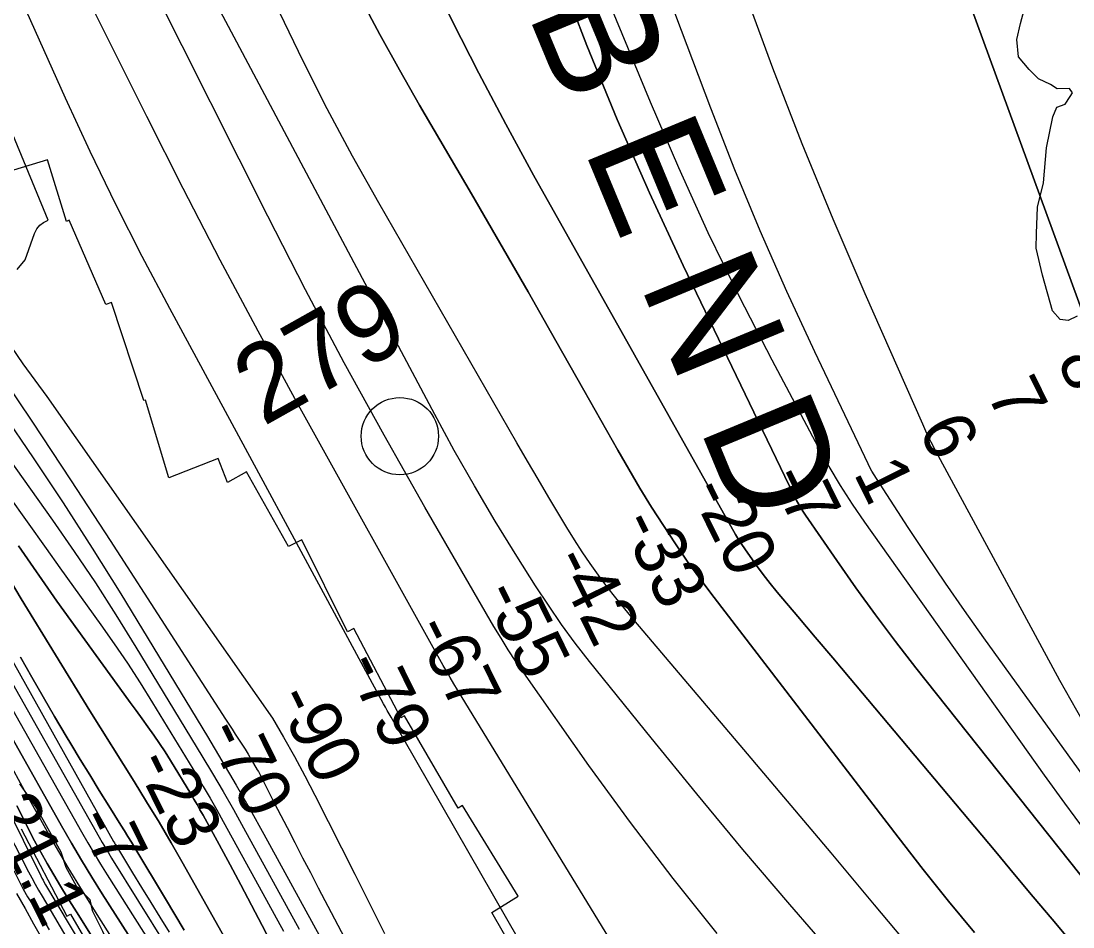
# Model space of a CAD drawing. Extents: x 3187622 to 3225504, y 800805 to 826213.
# Drawn here: x 3198035 to 3199396, y 818665 to 819837 of the extents above; entities that cross this region are included whole.
import ezdxf

# ---------------------------------------------------------------- set-up
doc = ezdxf.new("R2010")
doc.units = 0
for name, color, linetype in [('V-RIVR-EDGE', 7, 'Continuous'), ('V-RIVR-IDEN', 7, 'Continuous'), ('V-RIVR-MILE', 7, 'Continuous'), ('V-RIVR-RANG', 7, 'Continuous'), ('V-RRAP-RVMT', 7, 'Continuous'), ('V-SITE-VEGE', 7, 'Continuous'), ('V-TOPO-DPTH', 7, 'Continuous'), ('V-TOPO-MAJR', 7, 'Continuous'), ('V-TOPO-MINR', 7, 'Continuous'), ('V-TOPO-WATR', 7, 'Continuous')]:
    doc.layers.add(name, color=color, linetype=linetype)

msp = doc.modelspace()

# ---------------------------------------------------------------- linework, layer by layer
at = {"layer": 'V-RIVR-EDGE'}
for points in [[(3199401.5, 819455.2), (3199389.8, 819449.6), (3199379.3, 819450.9), (3199369.4, 819462.3), (3199356.4, 819508.4), (3199348.3, 819543.2), (3199348.7, 819562.3), (3199350.1, 819596.2), (3199358, 819627.9), (3199361.6, 819673.1), (3199370, 819713.1), (3199375.2, 819725.7), (3199385.7, 819729.5), (3199392.2, 819739.5), (3199395.3, 819744.3), (3199391.4, 819750), (3199375.7, 819749.6), (3199367, 819755.2), (3199351.4, 819762.2), (3199339.3, 819774.4), (3199325.4, 819791), (3199323.3, 819813.2), (3199328.1, 819834), (3199332.9, 819851.8)], [(3198032.9, 818850.3), (3198055, 818818.9), (3198086.6, 818762.3), (3198093.1, 818742.3), (3198106.5, 818718.4), (3198123.9, 818700.5), (3198126.9, 818686.2), (3198140.3, 818659.6), (3198150.7, 818637.9), (3198153.7, 818624.8), (3198170.2, 818619.1), (3198180.6, 818600.4), (3198185.3, 818583.4), (3198198.3, 818559.9)]]:
    msp.add_lwpolyline(points, dxfattribs=at)
at = {"layer": 'V-RIVR-MILE'}
msp.add_circle((3198525.1, 819300), 50, dxfattribs=at)
at = {"layer": 'V-RRAP-RVMT'}
for p, q in [((3198069.1, 819657.7), (3198025.3, 819644.3)), ((3198093.6, 819577.8), (3198069.1, 819657.7)), ((3198097.4, 819579.5), (3198093.6, 819577.8)), ((3198144.8, 819470.4), (3198097.4, 819579.5)), ((3198152, 819472.8), (3198144.8, 819470.4)), ((3198193.7, 819346.2), (3198152, 819472.8)), ((3198196, 819346.8), (3198193.7, 819346.2)), ((3198226.1, 819246), (3198196, 819346.8)), ((3198289.9, 819271), (3198226.1, 819246)), ((3198302, 819240.3), (3198289.9, 819271)), ((3198326.8, 819254.1), (3198302, 819240.3)), ((3198381.1, 819157.2), (3198326.8, 819254.1)), ((3198398.4, 819165.8), (3198381.1, 819157.2)), ((3198457.3, 819047), (3198398.4, 819165.8)), ((3198465.6, 819051.2), (3198457.3, 819047)), ((3198526.5, 818935.5), (3198465.6, 819051.2)), ((3198531, 818938.2), (3198526.5, 818935.5)), ((3198600.4, 818818.8), (3198531, 818938.2)), ((3198606.1, 818822.3), (3198600.4, 818818.8)), ((3198678.1, 818704.9), (3198606.1, 818822.3)), ((3198035, 818791.8), (3198094.1, 818679)), ((3198644.3, 818683.7), (3198678.1, 818704.9)), ((3198094.1, 818679), (3198099, 818681.6)), ((3198099, 818681.6), (3198172, 818556)), ((3198712.3, 818564.4), (3198644.3, 818683.7))]:
    msp.add_line(p, q, dxfattribs=at)
at = {"layer": 'V-SITE-VEGE'}
for p, q in [((3198025.5, 818738.3), (3198037.9, 818713.8)), ((3198037.9, 818713.8), (3198043.2, 818704.1)), ((3198043.2, 818704.1), (3198051.4, 818691.7)), ((3198051.4, 818691.7), (3198054.7, 818686.8)), ((3198054.7, 818686.8), (3198060.8, 818679.2)), ((3198060.8, 818679.2), (3198064.1, 818674)), ((3198064.1, 818674), (3198071.5, 818661.5))]:
    msp.add_line(p, q, dxfattribs=at)
at = {"layer": 'V-TOPO-DPTH'}
for points in [[(3198519, 820692.6), (3198538.7, 820598.2), (3198560.1, 820504.1), (3198646.5, 820144.6), (3198652.7, 820120.9), (3198659.4, 820097.4), (3198666.9, 820074.1), (3198675, 820050.9), (3198729.9, 819902.4), (3198767.2, 819805.7), (3198806.3, 819709.8), (3198848.1, 819615), (3198891.7, 819521), (3199035, 819223.7), (3199038.4, 819217), (3199042, 819210.5), (3199045.8, 819204.1), (3199049.9, 819197.8), (3199090.3, 819139), (3199115, 819103.7), (3199140.3, 819068.8), (3199166.3, 819034.4), (3199192.8, 819000.3), (3199485.2, 818632.6)], [(3199485.2, 818632.6), (3199192.8, 819000.3), (3199166.3, 819034.4), (3199140.3, 819068.8), (3199115, 819103.7), (3199090.3, 819139), (3199049.9, 819197.8), (3199045.8, 819204.1), (3199042, 819210.5), (3199038.4, 819217), (3199035, 819223.7), (3198891.7, 819521), (3198848.1, 819615), (3198806.3, 819709.8), (3198767.2, 819805.7), (3198729.9, 819902.4), (3198675, 820050.9), (3198666.9, 820074.1), (3198659.4, 820097.4), (3198652.7, 820120.9), (3198646.5, 820144.6), (3198560.1, 820504.1), (3198538.7, 820598.2), (3198519, 820692.6)], [(3199048.9, 820667.9), (3199069.1, 820567.3), (3199090.1, 820466.9), (3199124.2, 820309.6), (3199129.1, 820288.1), (3199134.3, 820266.6), (3199140, 820245.3), (3199146, 820224), (3199173.7, 820129.8), (3199194.4, 820061.6), (3199216, 819993.8), (3199238.9, 819926.4), (3199262.7, 819859.3), (3199420, 819428.5)], [(3199048.9, 820667.9), (3199069.1, 820567.3), (3199090.1, 820466.9), (3199124.2, 820309.6), (3199129.1, 820288.1), (3199134.3, 820266.6), (3199140, 820245.3), (3199146, 820224), (3199173.7, 820129.8), (3199194.4, 820061.6), (3199216, 819993.8), (3199238.9, 819926.4), (3199262.7, 819859.3), (3199420, 819428.5)], [(3199525.8, 818699.1), (3199280.7, 819039.1), (3199255.6, 819074.4), (3199230.9, 819109.9), (3199206.7, 819145.8), (3199182.8, 819181.9), (3199141.6, 819245.3), (3199138.7, 819249.9), (3199135.9, 819254.6), (3199133.3, 819259.4), (3199130.9, 819264.3), (3199061.8, 819409.3), (3199025.9, 819487.1), (3198991.3, 819565.6), (3198958.7, 819644.8), (3198927.4, 819724.6), (3198781.7, 820111)], [(3199525.8, 818699.1), (3199280.7, 819039.1), (3199255.6, 819074.4), (3199230.9, 819109.9), (3199206.7, 819145.8), (3199182.8, 819181.9), (3199141.6, 819245.3), (3199138.7, 819249.9), (3199135.9, 819254.6), (3199133.3, 819259.4), (3199130.9, 819264.3), (3199061.8, 819409.3), (3199025.9, 819487.1), (3198991.3, 819565.6), (3198958.7, 819644.8), (3198927.4, 819724.6), (3198781.7, 820111)], [(3198560.7, 819904), (3198593.4, 819836.6), (3198627.1, 819769.7), (3198662.1, 819703.6), (3198698.1, 819637.9), (3198959.4, 819172.7), (3198960.7, 819170.6), (3198963.2, 819166.4), (3198964.6, 819164.4), (3198978.2, 819144.5), (3198986.5, 819132.6), (3198995.1, 819121), (3199004.1, 819109.6), (3199013.2, 819098.4), (3199039.9, 819066.9), (3199062.6, 819040.1), (3199085.2, 819013.2), (3199107.8, 818986.3), (3199130.4, 818959.4), (3199296, 818762.1), (3199320.3, 818733.1), (3199344.6, 818704.2), (3199368.9, 818675.2), (3199393.2, 818646.3)], [(3199393.2, 818646.3), (3199368.9, 818675.2), (3199344.6, 818704.2), (3199320.3, 818733.1), (3199296, 818762.1), (3199130.4, 818959.4), (3199107.8, 818986.3), (3199085.2, 819013.2), (3199062.6, 819040.1), (3199039.9, 819066.9), (3199013.2, 819098.4), (3199004.1, 819109.6), (3198995.1, 819121), (3198986.5, 819132.6), (3198978.2, 819144.5), (3198964.6, 819164.4), (3198963.2, 819166.4), (3198960.7, 819170.6), (3198959.4, 819172.7), (3198698.1, 819637.9), (3198662.1, 819703.6), (3198627.1, 819769.7), (3198593.4, 819836.6), (3198560.7, 819904)], [(3198474.5, 819866.1), (3198499.1, 819819.8), (3198524.5, 819774), (3198550.4, 819728.5), (3198617.7, 819613.4), (3198654.4, 819550.1), (3198690.9, 819486.8), (3198727.1, 819423.3), (3198763.2, 819359.6), (3198807, 819281.9), (3198821.2, 819257.2), (3198835.7, 819232.7), (3198850.7, 819208.4), (3198866, 819184.3), (3198881.7, 819160.6), (3198897.9, 819137.1), (3198914.6, 819114), (3198931.7, 819091.2), (3199169.7, 818781.2), (3199202.2, 818739.6), (3199235.1, 818698.5), (3199268.7, 818657.9)], [(3199268.7, 818657.9), (3199235.1, 818698.5), (3199202.2, 818739.6), (3199169.7, 818781.2), (3198931.7, 819091.2), (3198914.6, 819114), (3198897.9, 819137.1), (3198881.7, 819160.6), (3198866, 819184.3), (3198850.7, 819208.4), (3198835.7, 819232.7), (3198821.2, 819257.2), (3198807, 819281.9), (3198763.2, 819359.6), (3198727.1, 819423.3), (3198690.9, 819486.8), (3198654.4, 819550.1), (3198617.7, 819613.4), (3198550.4, 819728.5), (3198524.5, 819774), (3198499.1, 819819.8), (3198474.5, 819866.1)], [(3198379, 818508.1), (3198244.6, 818746.8), (3198229.2, 818773.7), (3198213.6, 818800.5), (3198197.5, 818827), (3198181.3, 818853.4), (3198124.1, 818944.8), (3198079.4, 819017), (3198035.2, 819089.5), (3197991.7, 819162.4)], [(3197991.7, 819162.4), (3198035.2, 819089.5), (3198079.4, 819017), (3198124.1, 818944.8), (3198181.3, 818853.4), (3198197.5, 818827), (3198213.6, 818800.5), (3198229.2, 818773.7), (3198244.6, 818746.8), (3198379, 818508.1)], [(3198393.1, 818577.3), (3198347, 818666.8), (3198333.3, 818693.2), (3198319.5, 818719.4), (3198305.5, 818745.6), (3198291.3, 818771.7), (3198270.4, 818809.9), (3198266.5, 818816.8), (3198262.7, 818823.6), (3198258.7, 818830.4), (3198254.6, 818837.2), (3198228.4, 818880.4), (3198221.4, 818891.5), (3198214.3, 818902.5), (3198206.9, 818913.3), (3198199.2, 818923.9), (3198191.5, 818934.5), (3198183.8, 818945.1), (3198176.1, 818955.6), (3198168.4, 818966.3), (3198081.4, 819086.5), (3198031.8, 819158.2)], [(3198031.8, 819158.2), (3198081.4, 819086.5), (3198168.4, 818966.3), (3198176.1, 818955.6), (3198183.8, 818945.1), (3198191.5, 818934.5), (3198199.2, 818923.9), (3198206.9, 818913.3), (3198214.3, 818902.5), (3198221.4, 818891.5), (3198228.4, 818880.4), (3198254.6, 818837.2), (3198258.7, 818830.4), (3198262.7, 818823.6), (3198266.5, 818816.8), (3198270.4, 818809.9), (3198291.3, 818771.7), (3198305.5, 818745.6), (3198319.5, 818719.4), (3198333.3, 818693.2), (3198347, 818666.8), (3198393.1, 818577.3)], [(3197962.8, 819088), (3198136.2, 818781.3), (3198140.1, 818774.4), (3198144.1, 818767.6), (3198148.1, 818760.9), (3198152.2, 818754.2), (3198256.7, 818586)], [(3197962.8, 819088), (3198136.2, 818781.3), (3198140.1, 818774.4), (3198144.1, 818767.6), (3198148.1, 818760.9), (3198152.2, 818754.2), (3198256.7, 818586)], [(3198246.2, 818660.9), (3198221.9, 818701.3), (3198182.2, 818767.4), (3198177.8, 818774.7), (3198173.3, 818782), (3198168.8, 818789.3), (3198164.3, 818796.6), (3198148.5, 818821.8), (3198136.1, 818841.8), (3198123.8, 818861.8), (3198111.6, 818881.8), (3198099.4, 818901.9), (3198093.3, 818912.1), (3198078.3, 818937.4), (3198063.4, 818962.8), (3198048.8, 818988.4), (3198034.4, 819014.1)], [(3198034.4, 819014.1), (3198048.8, 818988.4), (3198063.4, 818962.8), (3198078.3, 818937.4), (3198093.3, 818912.1), (3198099.4, 818901.9), (3198111.6, 818881.8), (3198123.8, 818861.8), (3198136.1, 818841.8), (3198148.5, 818821.8), (3198164.3, 818796.6), (3198168.8, 818789.3), (3198173.3, 818782), (3198177.8, 818774.7), (3198182.2, 818767.4), (3198221.9, 818701.3), (3198246.2, 818660.9)], [(3198520, 818113.5), (3198140.1, 818707.8), (3198126.5, 818729.5), (3198113.1, 818751.4), (3198100.1, 818773.5), (3198087.4, 818795.7), (3198024.7, 818907.2)], [(3198024.7, 818907.2), (3198087.4, 818795.7), (3198100.1, 818773.5), (3198113.1, 818751.4), (3198126.5, 818729.5), (3198140.1, 818707.8), (3198520, 818113.5)], [(3198126.1, 818653.6), (3198109.7, 818679.8), (3198094.7, 818703.7), (3198085.9, 818718), (3198077.2, 818732.5), (3198068.8, 818747.1), (3198060.6, 818761.8), (3198052.6, 818776.6), (3198044.8, 818791.5), (3198037.2, 818806.6), (3198029.7, 818821.7)]]:
    msp.add_lwpolyline(points, dxfattribs=at)
at = {"layer": 'V-TOPO-MAJR'}
for points in [[(3199195.5, 818626.5), (3199139.4, 818693.7), (3199083.1, 818760.9), (3199026.7, 818827.8), (3198970.2, 818894.7), (3198827.8, 819062.4), (3198816, 819076.6), (3198804.4, 819090.9), (3198793.1, 819105.5), (3198782, 819120.3), (3198771.3, 819135.3), (3198760.9, 819150.5), (3198750.9, 819166), (3198741.2, 819181.7), (3198732, 819197.1), (3198718, 819220.7), (3198704, 819244.3), (3198690.2, 819267.9), (3198676.5, 819291.6), (3198497.7, 819601.9), (3198463.8, 819662.3), (3198431, 819723.4), (3198399.8, 819785.2), (3198369.6, 819847.6)], [(3198030.1, 819515.5), (3198040.5, 819528), (3198052.3, 819562.3), (3198055.3, 819568.1), (3198059.1, 819573), (3198064.2, 819576.6), (3198070.2, 819579.3), (3197966.9, 819828.2)], [(3198018.4, 819223.7), (3198067.5, 819154.6), (3198085.1, 819129.9), (3198102.8, 819105.3), (3198120.4, 819080.7), (3198138.2, 819056.1), (3198155.6, 819031.3), (3198172.7, 819006.3), (3198189.1, 818980.9), (3198205.1, 818955.2), (3198261.8, 818861.9), (3198270.8, 818846.9), (3198279.6, 818831.9), (3198288.2, 818816.8), (3198296.6, 818801.6), (3198342.9, 818717), (3198374.4, 818659.4)], [(3198029.2, 818708.5), (3198040.1, 818688.8), (3198051.2, 818669.1), (3198170.2, 818460.4)]]:
    msp.add_lwpolyline(points, dxfattribs=at)
at = {"layer": 'V-TOPO-MINR'}
for points in [[(3199408.3, 818932.1), (3199379.2, 818983.9), (3199224.4, 819269.3), (3199218.4, 819280.6), (3199212.6, 819292.1), (3199207.1, 819303.7), (3199201.8, 819315.4), (3199127, 819484.3), (3199085.6, 819580.9), (3199045.5, 819678.1), (3199007.7, 819776.2), (3198971.3, 819874.8), (3198875.3, 820144.1), (3198870.8, 820157.6), (3198866.9, 820171.3), (3198863.5, 820185.1), (3198860.7, 820199.1), (3198834.3, 820345.3), (3198832.7, 820358.6), (3198832, 820372), (3198832.7, 820385.3), (3198837.6, 821114.9)], [(3199485.2, 818632.6), (3199192.8, 819000.3), (3199166.3, 819034.4), (3199140.3, 819068.8), (3199115, 819103.7), (3199090.3, 819139), (3199049.9, 819197.8), (3199045.8, 819204.1), (3199042, 819210.5), (3199038.4, 819217), (3199035, 819223.7), (3198891.7, 819521), (3198848.1, 819615), (3198806.3, 819709.8), (3198767.2, 819805.7), (3198729.9, 819902.4), (3198675, 820050.9), (3198666.9, 820074.1), (3198659.4, 820097.4), (3198652.7, 820120.9), (3198646.5, 820144.6), (3198560.1, 820504.1), (3198538.7, 820598.2), (3198519, 820692.6)], [(3199525.8, 818699.1), (3199280.7, 819039.1), (3199255.6, 819074.4), (3199230.9, 819109.9), (3199206.7, 819145.8), (3199182.8, 819181.9), (3199141.6, 819245.3), (3199138.7, 819249.9), (3199135.9, 819254.6), (3199133.3, 819259.4), (3199130.9, 819264.3), (3199061.8, 819409.3), (3199025.9, 819487.1), (3198991.3, 819565.6), (3198958.7, 819644.8), (3198927.4, 819724.6), (3198781.7, 820111)], [(3199412, 818789), (3199385.4, 818825.2), (3199359.1, 818861.6), (3199126.8, 819188.6), (3199110.7, 819212.1), (3199095.3, 819236.1), (3199080.7, 819260.6), (3199066.9, 819285.5), (3199006.9, 819398.2), (3198964.7, 819480.4), (3198924.1, 819563.3), (3198886, 819647.3), (3198849.5, 819732.1), (3198697.7, 820098.9)], [(3198834.6, 818587), (3198599.6, 818972), (3198594.9, 818979.8), (3198590.3, 818987.6), (3198585.8, 818995.5), (3198581.3, 819003.5), (3198392, 819344.2), (3198341.9, 819435.8), (3198292.7, 819527.8), (3198244.7, 819620.6), (3198197.6, 819713.7), (3198120.7, 819868.3), (3198112.9, 819884.6), (3198105.3, 819901), (3198098.1, 819917.6), (3198091.1, 819934.3), (3198031.3, 820082.8)], [(3199091.1, 818623.2), (3199029.8, 818693.9), (3198969, 818765.1), (3198909.3, 818837.1), (3198850.2, 818909.6), (3198770.6, 819008.6), (3198752.1, 819032.4), (3198734.3, 819056.5), (3198717.2, 819081.2), (3198700.7, 819106.4), (3198676.4, 819145), (3198648.6, 819190.1), (3198621.6, 819235.6), (3198595.5, 819281.6), (3198570.2, 819328.1), (3198249.3, 819931.7)], [(3199393.2, 818646.3), (3199368.9, 818675.2), (3199344.6, 818704.2), (3199320.3, 818733.1), (3199296, 818762.1), (3199130.4, 818959.4), (3199107.8, 818986.3), (3199085.2, 819013.2), (3199062.6, 819040.1), (3199039.9, 819066.9), (3199013.2, 819098.4), (3199004.1, 819109.6), (3198995.1, 819121), (3198986.5, 819132.6), (3198978.2, 819144.5), (3198964.6, 819164.4), (3198963.2, 819166.4), (3198960.7, 819170.6), (3198959.4, 819172.7), (3198698.1, 819637.9), (3198662.1, 819703.6), (3198627.1, 819769.7), (3198593.4, 819836.6), (3198560.7, 819904)], [(3198878.7, 818300.2), (3198513.8, 818936.3), (3198511.3, 818940.7), (3198508.8, 818945), (3198506.4, 818949.4), (3198504, 818953.8), (3198227.3, 819465.2), (3198191.9, 819532.3), (3198157.5, 819599.9), (3198124.6, 819668.3), (3198092.7, 819737.2), (3198036.3, 819862.3), (3198033.4, 819869)], [(3198935.8, 818656.7), (3198878.6, 818727.6), (3198823.5, 818800.2), (3198769.8, 818873.9), (3198685.3, 818993.8), (3198675.2, 819008.5), (3198665.4, 819023.4), (3198656, 819038.5), (3198646.8, 819053.8), (3198557.5, 819208.1), (3198504.7, 819301.2), (3198453, 819394.8), (3198403.1, 819489.4), (3198354.2, 819584.6), (3198206.5, 819879.1)], [(3199268.7, 818657.9), (3199235.1, 818698.5), (3199202.2, 818739.6), (3199169.7, 818781.2), (3198931.7, 819091.2), (3198914.6, 819114), (3198897.9, 819137.1), (3198881.7, 819160.6), (3198866, 819184.3), (3198850.7, 819208.4), (3198835.7, 819232.7), (3198821.2, 819257.2), (3198807, 819281.9), (3198763.2, 819359.6), (3198727.1, 819423.3), (3198690.9, 819486.8), (3198654.4, 819550.1), (3198617.7, 819613.4), (3198550.4, 819728.5), (3198524.5, 819774), (3198499.1, 819819.8), (3198474.5, 819866.1)], [(3197692.4, 819474), (3198060.4, 818731.3), (3198061.9, 818728.3), (3198063.4, 818725.4), (3198065.1, 818722.5), (3198066.7, 818719.6), (3198161.1, 818561.1)], [(3198007.6, 819436.6), (3198037.5, 819393.6), (3198068.5, 819351.2), (3198360.5, 818935.1), (3198374.7, 818910.5), (3198388.6, 818885.7), (3198402, 818860.6), (3198415.1, 818835.4), (3198467, 818733.2), (3198505.3, 818656.5)], [(3197997.2, 819396), (3198048.9, 819319.5), (3198099.8, 819242.4), (3198150.3, 819165.1), (3198299.6, 818933.9), (3198303.8, 818927.4), (3198308, 818920.9), (3198312.2, 818914.5), (3198316.5, 818908), (3198320.6, 818901.5), (3198324.8, 818895), (3198328.8, 818888.4), (3198332.8, 818881.8), (3198340.6, 818868.4), (3198342, 818866), (3198343.4, 818863.5), (3198344.8, 818860.9), (3198346.1, 818858.4), (3198351.3, 818848.1), (3198355.2, 818840.4), (3198359.2, 818832.7), (3198363.1, 818825), (3198367, 818817.3), (3198379.1, 818793.7), (3198389.1, 818774.2), (3198399.2, 818754.7), (3198409.3, 818735.3), (3198419.4, 818715.8), (3198626.7, 818322)], [(3197733.5, 819342.4), (3198044.8, 818736.4), (3198049, 818728.4), (3198053.3, 818720.4), (3198057.7, 818712.5), (3198062.2, 818704.7), (3198457.6, 818031.1)], [(3198011.3, 819329.6), (3198050.8, 819272.1), (3198089.6, 819214), (3198127.2, 819155.3), (3198164, 819096), (3198276.2, 818911.3), (3198294.9, 818880), (3198313.4, 818848.6), (3198331.4, 818816.9), (3198349.1, 818785.1), (3198502.3, 818505.7)], [(3198018.7, 819271.4), (3198047.1, 819231.3), (3198075.6, 819191.2), (3198103.6, 819150.9), (3198131.1, 819110.2), (3198157.6, 819068.8), (3198183.6, 819027.1), (3198269, 818886.6), (3198282.8, 818863.5), (3198296.5, 818840.3), (3198309.8, 818816.9), (3198322.9, 818793.3), (3198394.8, 818662)], [(3197891.8, 819244.6), (3198154.6, 818775.8), (3198155.8, 818773.8), (3198156.4, 818772.8), (3198157, 818771.7), (3198179.1, 818735.2), (3198190.9, 818716), (3198202.7, 818696.7), (3198214.6, 818677.6), (3198226.6, 818658.5)], [(3197991.7, 819162.4), (3198035.2, 819089.5), (3198079.4, 819017), (3198124.1, 818944.8), (3198181.3, 818853.4), (3198197.5, 818827), (3198213.6, 818800.5), (3198229.2, 818773.7), (3198244.6, 818746.8), (3198379, 818508.1)], [(3198031.8, 819158.2), (3198081.4, 819086.5), (3198168.4, 818966.3), (3198176.1, 818955.6), (3198183.8, 818945.1), (3198191.5, 818934.5), (3198199.2, 818923.9), (3198206.9, 818913.3), (3198214.3, 818902.5), (3198221.4, 818891.5), (3198228.4, 818880.4), (3198254.6, 818837.2), (3198258.7, 818830.4), (3198262.7, 818823.6), (3198266.5, 818816.8), (3198270.4, 818809.9), (3198291.3, 818771.7), (3198305.5, 818745.6), (3198319.5, 818719.4), (3198333.3, 818693.2), (3198347, 818666.8), (3198393.1, 818577.3)], [(3197962.8, 819088), (3198136.2, 818781.3), (3198140.1, 818774.4), (3198144.1, 818767.6), (3198148.1, 818760.9), (3198152.2, 818754.2), (3198256.7, 818586)], [(3198034.4, 819014.1), (3198048.8, 818988.4), (3198063.4, 818962.8), (3198078.3, 818937.4), (3198093.3, 818912.1), (3198099.4, 818901.9), (3198111.6, 818881.8), (3198123.8, 818861.8), (3198136.1, 818841.8), (3198148.5, 818821.8), (3198164.3, 818796.6), (3198168.8, 818789.3), (3198173.3, 818782), (3198177.8, 818774.7), (3198182.2, 818767.4), (3198221.9, 818701.3), (3198246.2, 818660.9)], [(3198009.1, 818972.1), (3198113.2, 818788), (3198121.3, 818774), (3198129.5, 818760), (3198137.9, 818746.1), (3198146.5, 818732.4), (3198460.3, 818236.8)], [(3198015.4, 818885.5), (3198041.5, 818837.4), (3198060, 818804.1), (3198077.6, 818773), (3198095.5, 818742.1), (3198114, 818711.6), (3198132.9, 818681.2), (3198213.4, 818554.2)], [(3198029.7, 818821.7), (3198037.2, 818806.6), (3198044.8, 818791.5), (3198052.6, 818776.6), (3198060.6, 818761.8), (3198068.8, 818747.1), (3198077.2, 818732.5), (3198085.9, 818718), (3198094.7, 818703.7), (3198109.7, 818679.8), (3198126.1, 818653.6)]]:
    msp.add_lwpolyline(points, dxfattribs=at)
at = {"layer": 'V-TOPO-WATR'}
for points in [[(3199420, 819428.5), (3199262.7, 819859.3), (3199238.9, 819926.4), (3199216, 819993.8), (3199194.4, 820061.6), (3199173.7, 820129.8), (3199146, 820224), (3199140, 820245.3), (3199134.3, 820266.6), (3199129.1, 820288.1), (3199124.2, 820309.6), (3199090.1, 820466.9), (3199069.1, 820567.3), (3199048.9, 820667.9)], [(3198024.7, 818907.2), (3198087.4, 818795.7), (3198100.1, 818773.5), (3198113.1, 818751.4), (3198126.5, 818729.5), (3198140.1, 818707.8), (3198520, 818113.5)]]:
    msp.add_lwpolyline(points, dxfattribs=at)

# ---------------------------------------------------------------- texts
at = {"layer": 'V-RIVR-IDEN'}
for s, height, rotation, p in [('B E N D', 150, 292.5256, (3198689.8, 819847.3)), ('279', 100, 29.3311, (3198348.2, 819312.1))]:
    msp.add_text(s, height=height, rotation=rotation, dxfattribs=at).set_placement(p)
at = {"layer": 'V-RIVR-RANG'}
for s, rotation, p in [('8', 296.2369, (3199374.2, 819398)), ('7', 296.2369, (3199283.6, 819355.6)), ('6', 296.2369, (3199195.1, 819309)), ('-7', 296.2369, (3199002.9, 819246.6)), ('1', 296.2369, (3199111.6, 819252.3)), ('-20', 296.2369, (3198899.8, 819229.6)), ('-33', 296.2369, (3198808.8, 819188)), ('-42', 296.2369, (3198721, 819139.9)), ('-55', 296.2369, (3198630.8, 819096.7)), ('-67', 296.2369, (3198541.6, 819051.5)), ('-79', 296.2369, (3198453, 819005.1)), ('-90', 296.2369, (3198363, 818961.4)), ('-70', 296.2369, (3198273.1, 818917.6)), ('-23', 296.2369, (3198181.2, 818877.9)), ('21.1', 296.1083, (3197988, 818818)), ('-7', 296.2369, (3198106, 818804.3))]:
    msp.add_text(s, height=67, rotation=rotation, dxfattribs=at).set_placement(p)

doc.saveas('drawing.dxf')
